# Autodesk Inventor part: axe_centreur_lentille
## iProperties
Created: 2011-01
Part Number: axe_centreur_lentille
Document SubType Name: Modeling
Designer: eric
Density: 1 g/cm^3
Mass: 1.70574 g
Surface Area: 9.51612 cm^2
Volume: 1.70574 cm^3
Author: eric
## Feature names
1. Base1
